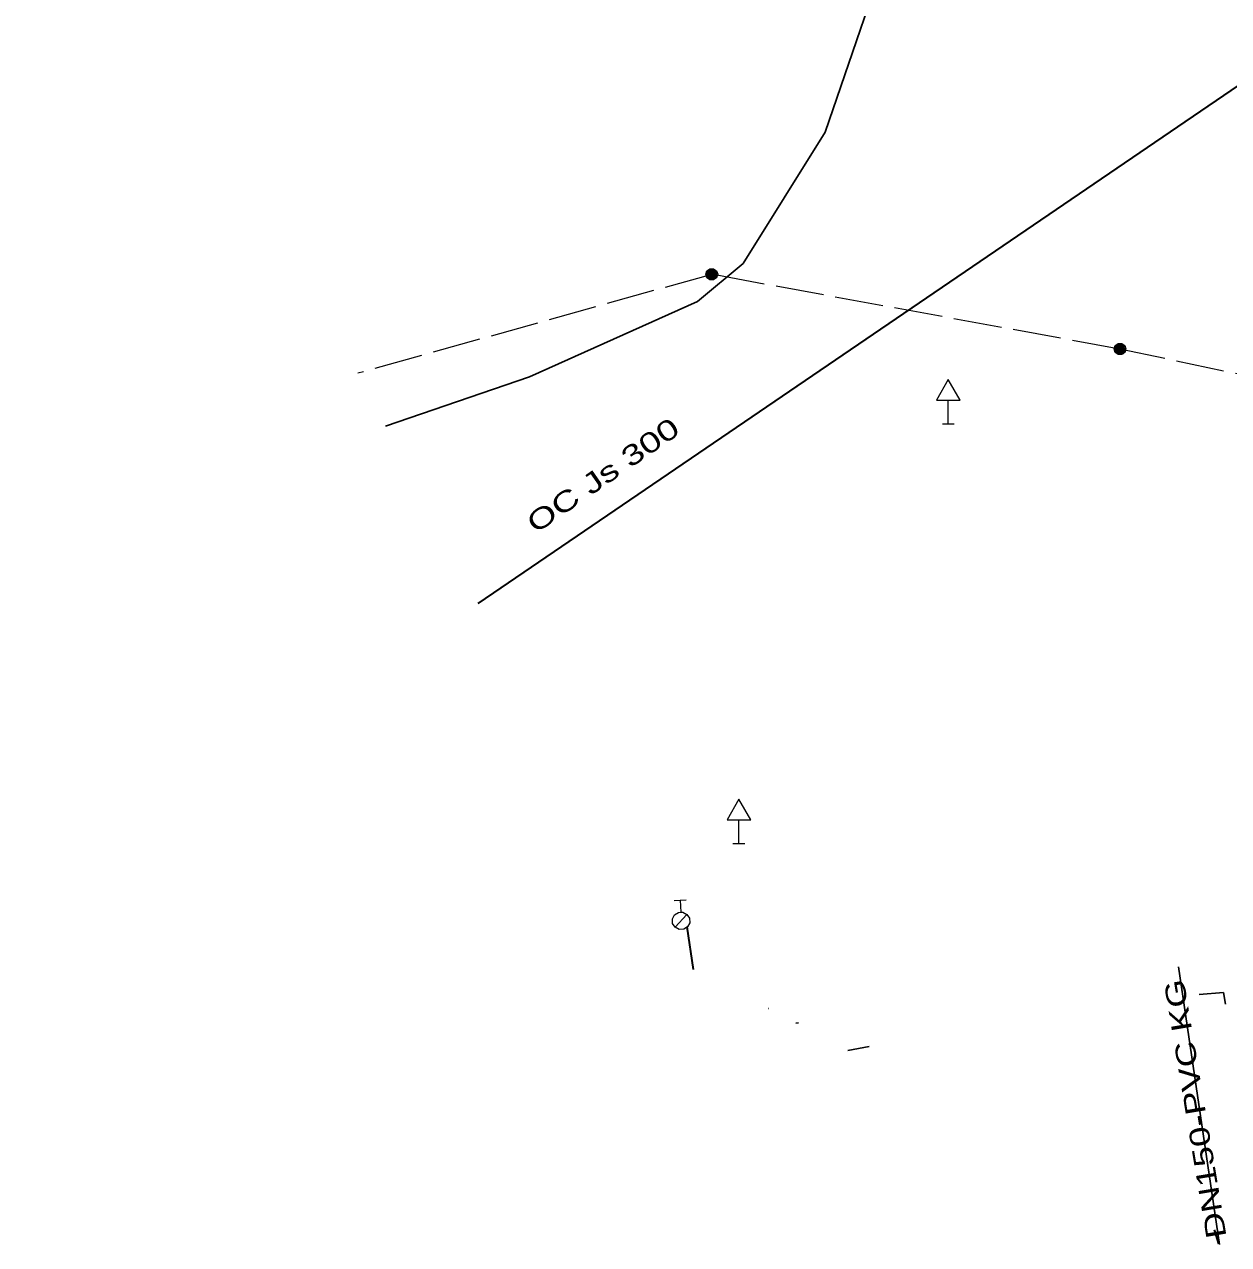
# Model space of a CAD drawing. Extents: x -763495 to -763378, y -1031793 to -1031652.
# Drawn here: x -763495.2 to -763444.2, y -1031775.6 to -1031723.9 of the extents above; entities that cross this region are included whole.
import ezdxf
from ezdxf.enums import TextEntityAlignment as Align

# ---------------------------------------------------------------- set-up
doc = ezdxf.new("R2010")
doc.units = 0
doc.header["$LTSCALE"] = 0.34
doc.linetypes.add('LONG_DASH_SHORT_DASH', pattern=[9.9, 6, -1.2, 1.5, -1.2])
doc.linetypes.add('LONG_DASHED', pattern=[7.5, 6, -1.5])
for name, color, linetype, lineweight in [('23', 7, 'Continuous', 13), ('33', 7, 'Continuous', 13), ('40', 7, 'Continuous', 13), ('43', 7, 'Continuous', 25), ('44', 7, 'Continuous', 35), ('47', 7, 'LONG_DASH_SHORT_DASH', 25), ('48', 7, 'Continuous', 25), ('53', 7, 'Continuous', 25), ('59', 7, 'LONG_DASHED', 13)]:
    doc.layers.add(name, color=color, linetype=linetype, lineweight=lineweight)

msp = doc.modelspace()

# ---------------------------------------------------------------- linework, layer by layer
at = {"layer": '23'}
for p, q in [((-763456.34, -1031740.84), (-763455.84, -1031740.84)), ((-763465.2, -1031758.59), (-763464.7, -1031758.59))]:
    msp.add_line(p, q, dxfattribs=at)
for points in [[(-763456.09, -1031740.84), (-763456.09, -1031739.84), (-763455.59, -1031739.84), (-763456.09, -1031738.965), (-763456.59, -1031739.84), (-763456.09, -1031739.84)], [(-763464.95, -1031758.59), (-763464.95, -1031757.59), (-763464.45, -1031757.59), (-763464.95, -1031756.715), (-763465.45, -1031757.59), (-763464.95, -1031757.59)]]:
    msp.add_lwpolyline(points, dxfattribs=at)
at = {"layer": '33'}
for p, q in [((-763467.682, -1031760.994), (-763467.182, -1031760.973)), ((-763467.146, -1031761.587), (-763467.644, -1031762.128))]:
    msp.add_line(p, q, dxfattribs=at)
msp.add_lwpolyline([(-763467.432, -1031760.983), (-763467.41, -1031761.498), (-763467.315, -1031761.494), (-763467.146, -1031761.587), (-763467.04, -1031761.748), (-763467.031, -1031761.943), (-763467.119, -1031762.116), (-763467.285, -1031762.218), (-763467.48, -1031762.227), (-763467.649, -1031762.134), (-763467.756, -1031761.973), (-763467.764, -1031761.778), (-763467.671, -1031761.609), (-763467.51, -1031761.502), (-763467.41, -1031761.498)], dxfattribs=at)
at = {"layer": '40'}
for points in [[(-763466.175, -1031734.28), (-763466.02, -1031734.28), (-763465.895, -1031734.37), (-763465.845, -1031734.515), (-763465.895, -1031734.66), (-763466.02, -1031734.75), (-763466.175, -1031734.75), (-763466.3, -1031734.66), (-763466.35, -1031734.515), (-763466.3, -1031734.37), (-763466.175, -1031734.28), (-763466.16, -1031734.3), (-763466.04, -1031734.3), (-763465.96, -1031734.34), (-763466.24, -1031734.34), (-763466.28, -1031734.38), (-763465.92, -1031734.38), (-763465.92, -1031734.42), (-763466.28, -1031734.42), (-763466.3, -1031734.46), (-763465.9, -1031734.46), (-763465.88, -1031734.5), (-763466.32, -1031734.5), (-763466.32, -1031734.54), (-763465.88, -1031734.54), (-763465.895, -1031734.58), (-763466.3, -1031734.58), (-763466.295, -1031734.62), (-763465.89, -1031734.62), (-763465.915, -1031734.66), (-763466.275, -1031734.66), (-763466.235, -1031734.7), (-763465.955, -1031734.7), (-763466.01, -1031734.74), (-763466.18, -1031734.74)], [(-763448.905, -1031737.44), (-763448.75, -1031737.44), (-763448.625, -1031737.53), (-763448.575, -1031737.675), (-763448.625, -1031737.82), (-763448.75, -1031737.91), (-763448.905, -1031737.91), (-763449.03, -1031737.82), (-763449.08, -1031737.675), (-763449.03, -1031737.53), (-763448.905, -1031737.44), (-763448.89, -1031737.46), (-763448.77, -1031737.46), (-763448.69, -1031737.5), (-763448.97, -1031737.5), (-763449.01, -1031737.54), (-763448.65, -1031737.54), (-763448.65, -1031737.58), (-763449.01, -1031737.58), (-763449.03, -1031737.62), (-763448.63, -1031737.62), (-763448.61, -1031737.66), (-763449.05, -1031737.66), (-763449.05, -1031737.7), (-763448.61, -1031737.7), (-763448.625, -1031737.74), (-763449.03, -1031737.74), (-763449.025, -1031737.78), (-763448.62, -1031737.78), (-763448.645, -1031737.82), (-763449.005, -1031737.82), (-763448.965, -1031737.86), (-763448.685, -1031737.86), (-763448.74, -1031737.9), (-763448.91, -1031737.9)]]:
    msp.add_lwpolyline(points, dxfattribs=at)
at = {"layer": '43', "lineweight": 35}
msp.add_line((-763466.872, -1031763.923), (-763467.14, -1031762.11), dxfattribs=at)
at = {"layer": '43'}
for p, q in [((-763444.611, -1031775.554), (-763446.35, -1031763.81)), ((-763462.54, -1031766.186), (-763462.43, -1031766.17))]:
    msp.add_line(p, q, dxfattribs=at)
at = {"layer": '43', "lineweight": 35}
msp.add_lwpolyline([(-763428.03, -1031715.48), (-763438.34, -1031722.78), (-763475.986, -1031748.441)], dxfattribs=at)
at = {"layer": '44'}
msp.add_line((-763444.843, -1031774.926), (-763444.664, -1031775.526), dxfattribs=at)
at = {"layer": '47'}
msp.add_line((-763460.335, -1031767.338), (-763459.437, -1031767.169), dxfattribs=at)
msp.add_lwpolyline([(-763444.369, -1031765.387), (-763444.445, -1031764.893), (-763445.478, -1031764.974)], dxfattribs=at)
at = {"layer": '48'}
msp.add_line((-763463.7, -1031765.57), (-763463.712, -1031765.574), dxfattribs=at)
msp.add_lwpolyline([(-763458.15, -1031719.33), (-763461.3, -1031728.5), (-763464.77, -1031734.06), (-763466.7, -1031735.67), (-763473.81, -1031738.85), (-763479.899, -1031740.933)], dxfattribs=at)
at = {"layer": '53'}
msp.add_lwpolyline([(-763495.174, -1031658.36), (-763488.91, -1031664.64), (-763481.87, -1031671.83), (-763475.67, -1031677.68), (-763470.62, -1031683.28), (-763468.06, -1031685.9), (-763467.68, -1031687.41), (-763466.73, -1031691.62), (-763466.86, -1031694.4), (-763466.86, -1031699.4), (-763466.38, -1031703.98), (-763464.85, -1031706.59), (-763460.17, -1031711.3), (-763458.07, -1031714.49), (-763458.15, -1031719.33), (-763461.3, -1031728.5), (-763464.77, -1031734.06), (-763466.7, -1031735.67), (-763473.81, -1031738.85), (-763479.899, -1031740.933)], dxfattribs=at)
at = {"layer": '59'}
msp.add_lwpolyline([(-763426.98, -1031742.31), (-763448.83, -1031737.68), (-763466.1, -1031734.52), (-763481.063, -1031738.7)], dxfattribs=at)

# ---------------------------------------------------------------- texts
at = {"layer": '33', "width": 1.4}
msp.add_text('OC Js 300', height=0.85, rotation=34.779, dxfattribs=at).set_placement((-763470.457, -1031743.361), align=Align.CENTER)
at = {"layer": '44', "width": 1.35}
msp.add_text('DN150-PVC KG', height=0.85, rotation=99.465, dxfattribs=at).set_placement((-763445.229, -1031769.746), align=Align.CENTER)

doc.saveas('drawing.dxf')
